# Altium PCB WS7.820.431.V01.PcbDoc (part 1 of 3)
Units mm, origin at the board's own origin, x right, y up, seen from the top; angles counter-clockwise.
Board outline 461 x 63.5 mm, 4 copper layers (Top Layer, Mid-Layer1, Mid-Layer 2, Bottom Layer); 379 components, 227 nets, 1092 pads, 3835 vias.
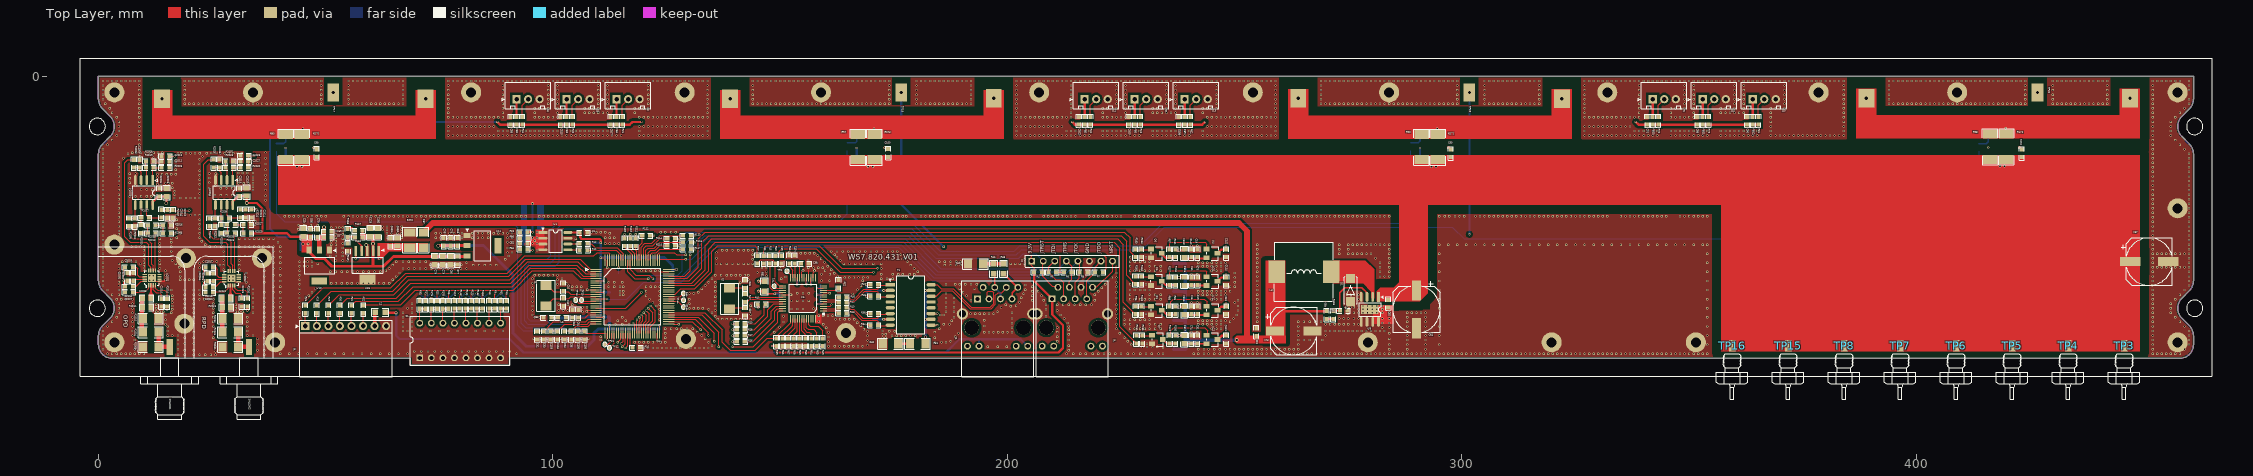
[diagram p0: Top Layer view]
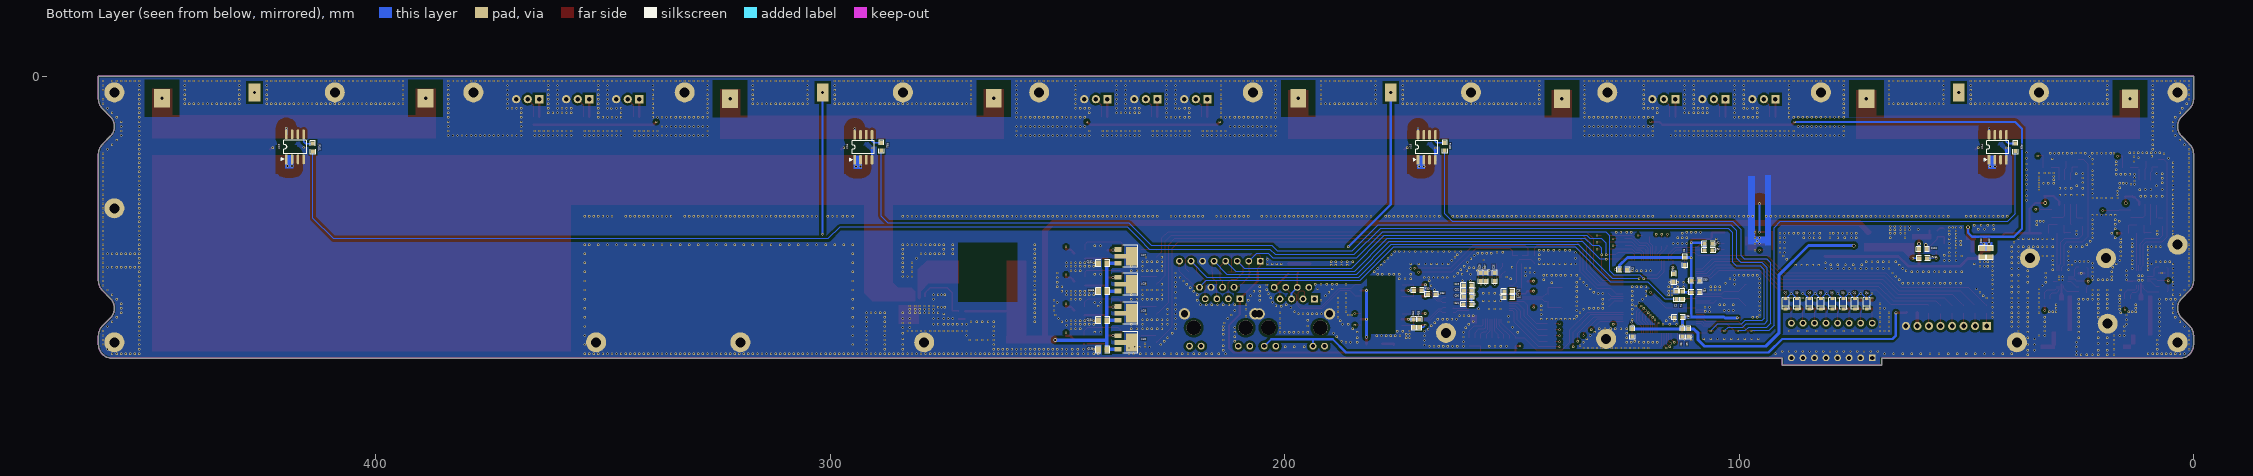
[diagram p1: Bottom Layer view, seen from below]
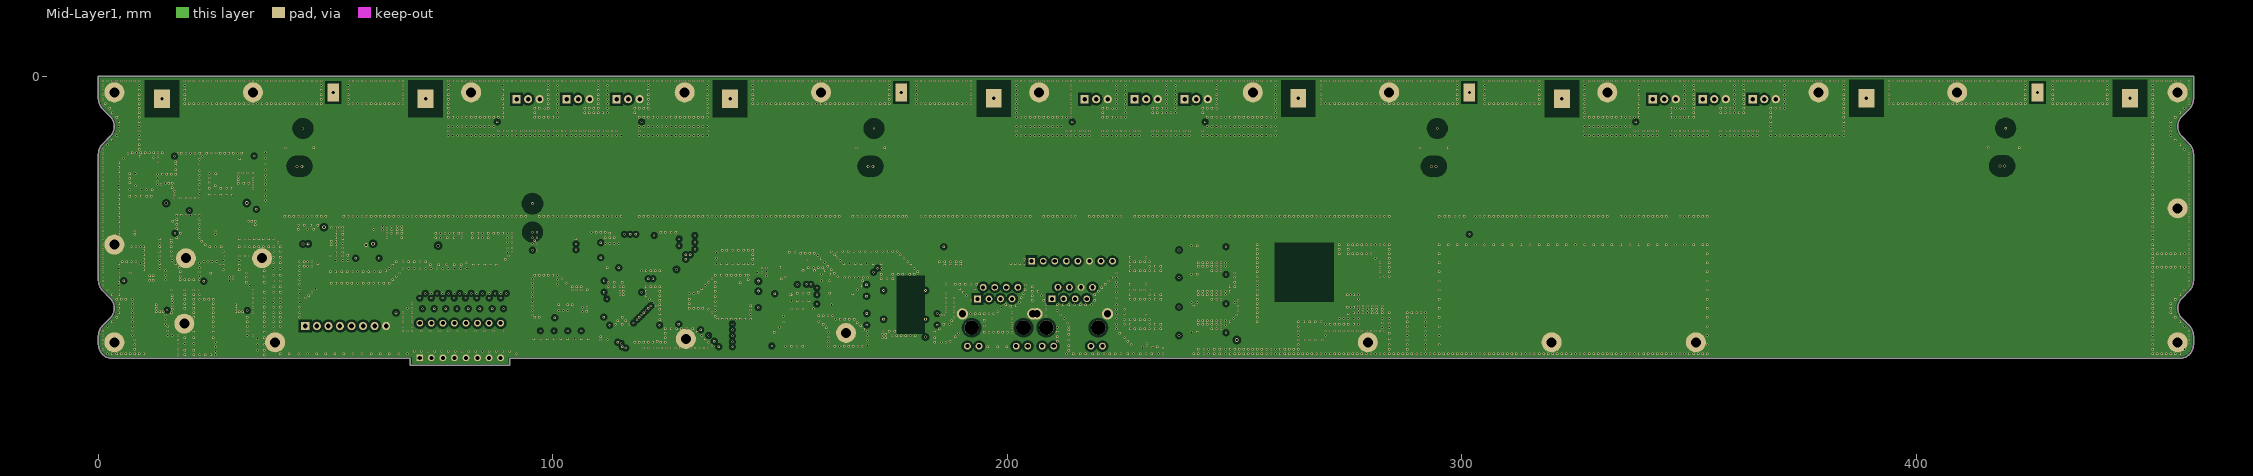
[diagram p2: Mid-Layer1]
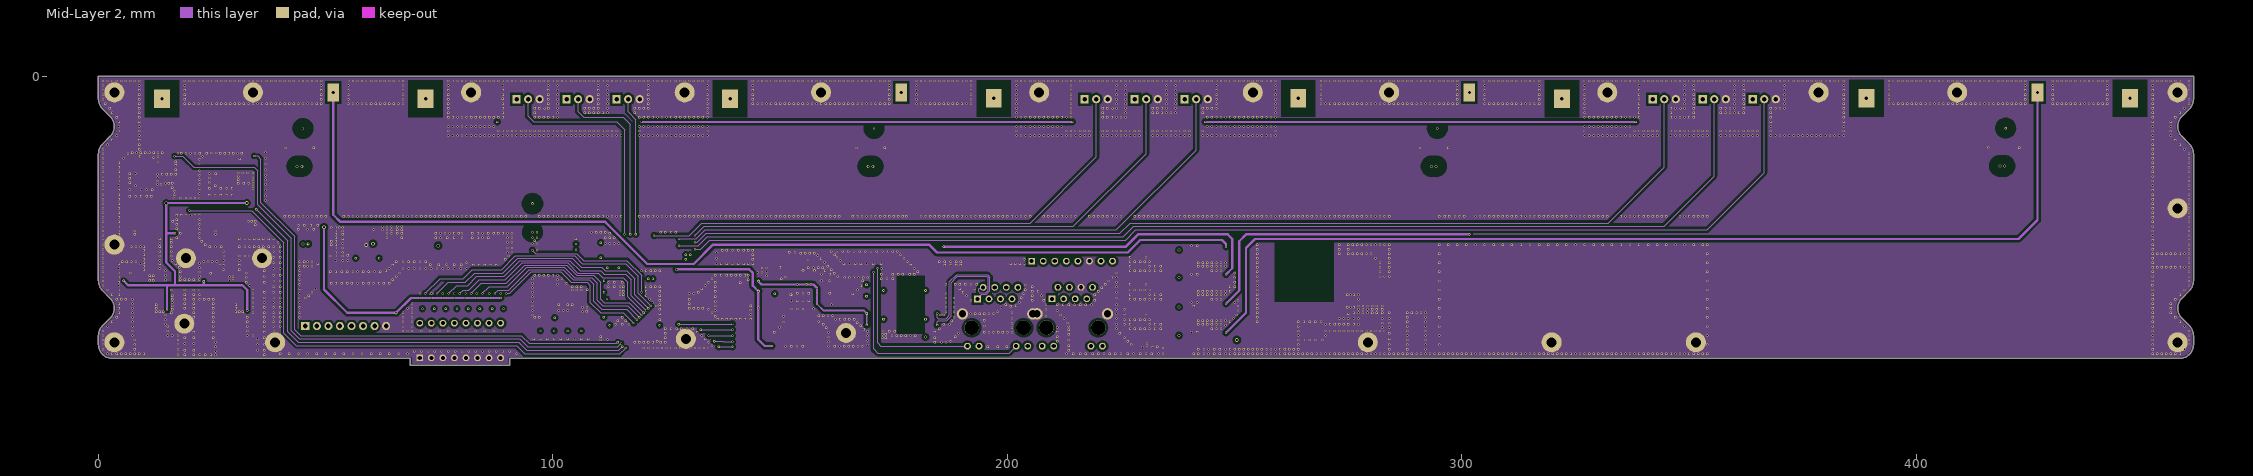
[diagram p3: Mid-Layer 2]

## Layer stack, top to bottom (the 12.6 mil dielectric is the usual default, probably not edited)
Top Solder: solder mask 0.0102, Solder Resist, Dk 3.5
Top Layer: signal copper 0.0356
Dielectric1: core 0.32, FR-4, Dk 4.8
Mid-Layer1: signal copper 0.0356
Dielectric3: prepreg 0.32, FR-4, Dk 4.8
Mid-Layer 2: signal copper 0.0356
Dielectric2: core 0.32, FR-4, Dk 4.8
Bottom Layer: signal copper 0.0356
Bottom Solder: solder mask 0.0102, Solder Resist, Dk 3.5

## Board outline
0,-57.04 cw(c3.066,-57.04) 0.898,-54.872 2.602,-53.168 ccw(c0.434,-51) 3.5,-51 ccw(c0.434,-51) 2.602,-48.832 0.898,-47.128 cw(c3.066,-44.96) 0,-44.96 0,-17.04 cw(c3.066,-17.04) 0.898,-14.872 2.602,-13.168 ccw(c0.434,-11) 3.5,-11 ccw(c0.434,-11) 2.602,-8.832 0.898,-7.128 cw(c3.066,-4.96) 0,-4.96 0,0 461,0 461,-4.96 cw(c457.934,-4.96) 460.102,-7.128 458.398,-8.832 ccw(c460.566,-11) 457.5,-11 ccw(c460.566,-11) 458.398,-13.168 460.102,-14.872 cw(c457.934,-17.04) 461,-17.04 461,-44.96 cw(c457.934,-44.96) 460.102,-47.128 458.398,-48.832 ccw(c460.566,-51) 457.5,-51 ccw(c460.566,-51) 458.398,-53.168 460.102,-54.872 cw(c457.934,-57.04) 461,-57.04 461,-59 cw(c458,-59) 458,-62 90.535,-62 90.535,-63.5 68.655,-63.5 68.655,-62 3,-62 cw(c3,-59) 0,-59

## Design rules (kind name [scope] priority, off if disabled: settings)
Clearance Clearance_4 [(InPolygon) vs InNetClass('50V')] p1: gap=2.032 ignorepadtopadclearanceinfootprint=FALSE except(0: Arc-Hole Track-Hole SMDPad-Hole THPad-Hole Via-Hole Fill-Hole Poly-Hole Region-Hole Text-Hole)
Clearance Clearance_3 [(InPolygon) vs isfill] p2: gap=1.016 ignorepadtopadclearanceinfootprint=FALSE except(0: Arc-Hole Track-Hole SMDPad-Hole THPad-Hole Via-Hole Fill-Hole Poly-Hole Region-Hole Text-Hole)
Clearance Clearance_2 [All vs OnLayer('Keep-Out Layer')] p3: gap=0.203 ignorepadtopadclearanceinfootprint=FALSE except(0: Arc-Hole Track-Hole SMDPad-Hole THPad-Hole Via-Hole Fill-Hole Poly-Hole Region-Hole Text-Hole)
Clearance Clearance_1 [All vs (InPolygon)] p4: gap=0.508 ignorepadtopadclearanceinfootprint=FALSE except(0: Arc-Hole Track-Hole SMDPad-Hole THPad-Hole Via-Hole Fill-Hole Poly-Hole Region-Hole Text-Hole)
Clearance [All] p5: gap=0.152 ignorepadtopadclearanceinfootprint=FALSE except(0: Arc-Hole Track-Hole SMDPad-Hole THPad-Hole Via-Hole Fill-Hole Poly-Hole Region-Hole Text-Hole)
ComponentClearance [All] p1: gap=0 collisioncheckmode=3 verticalgap=0 showdistances=FALSE
DiffPairsRouting DiffPair_DiffPairsRouting [All] p1: maxlimit=0.254 minlimit=0.191 mostfreqgap=0.191 toplayer_minwidth=0.191 toplayer_maxwidth=0.381 toplayer_prefwidth=0.191 midlayer1_minwidth=0.191 midlayer1_maxwidth=0.381 midlayer1_prefwidth=0.191 midlayer2_minwidth=0.191 midlayer2_maxwidth=0.381 midlayer2_prefwidth=0.191 bottomlayer_minwidth=0.191 bottomlayer_maxwidth=0.381 bottomlayer_prefwidth=0.191 maxuncoupledlength=12.7
DiffPairsRouting [All] p2: maxlimit=0.254 minlimit=0.254 mostfreqgap=0.254 toplayer_minwidth=0.381 toplayer_maxwidth=0.381 toplayer_prefwidth=0.381 midlayer1_minwidth=0.381 midlayer1_maxwidth=0.381 midlayer1_prefwidth=0.381 midlayer2_minwidth=0.381 midlayer2_maxwidth=0.381 midlayer2_prefwidth=0.381 bottomlayer_minwidth=0.381 bottomlayer_maxwidth=0.381 bottomlayer_prefwidth=0.381 maxuncoupledlength=12.7
HoleSize [All] p1: absolutevalues=TRUE maxlimit=10 minlimit=0.025 maxpercent=80.000 minpercent=20.000
HoleToHoleClearance [All] p1: gap=0 allowstackedmicrovias=TRUE
MinimumSolderMaskSliver [All] p1: minsoldermaskwidth=0
PlaneConnect [All] p1: planeconnectstyle=Direct reliefexpansion=0.508 reliefentries=4 reliefconductorwidth=0.254 reliefairgap=0.254
PolygonConnect [All] p1: connectstyle=Direct reliefconductorwidth=0.254 reliefentries=4 polygonreliefangle="90 Angle" airgapwidth=0.254
RoutingVias [All] p1: holewidth=0.305 width=0.508 viastyle="Through Hole" minholewidth=0.305 minwidth=0.508 maxholewidth=0.711 maxwidth=1.27
SilkToSilkClearance [All] p1: silktosilkclearance=0
SilkToSolderMaskClearance SilkscreenOverComponentPads [IsPad] p1: minsilkscreentomaskgap=0 clearancetoexposedcopper=TRUE
SolderMaskExpansion [All] p1: expansion=0 istentingtop=FALSE
Width DiffPair_Width [All] p1: maxlimit=2.54 minlimit=0.191 preferedwidth=0.191
Width [All] p2: maxlimit=1 minlimit=0.191 preferedwidth=0.254 midlayer1_maxwidth=0.254 midlayer2_maxwidth=0.254 minimp=50.000000 maximp=50.000000 favimp=50.000000
22 further rules are at their usual default settings.

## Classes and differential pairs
net class 50V: 28VIN 28VOUT1 28VOUT2 28VOUT3 28VOUT4
component class 1-MCU: C1 C2 C3 C4 C5 C6 C7 C8 C9 C10 C11 C71 C83 C90 C98 C99 C102 C107 C108 C109 C110 D2 D3 D4 D5 D6 D7 D8 D9 FB2 FB3 FB4 FB5 FB6 FB9 FB10 FB11 FB12 J1 J2 J3 J5 J6 J8 J9 J10 J11 J12 J13 J14 L2 R1 R2 R3 R4 R5 R6 R7 R8 R9 R10 R11 R12 R13 R14 R15 R16 R17 R18 R19 R20 R21 R22 R23 R24 R25 R26 R27 R28 R29 R30 R31 R32 R61 R62 R70 R77 R79 R81 R91 R109 R110 R111 R112 R113 R114 R115 R116 R117 R118 R119 R120 R121 R132 R133 R174 R175 R176 R177 S1 TP9 TP10 TP11 TP12 TP13 TP14 TP17 TP18 TP19 TP20 TP21 U1 U2 X1
component class 2-RJ45: C24 C25 C26 C27 C28 C29 C30 C31 C32 C33 C34 C35 C36 C37 C38 C39 C40 C41 C42 FB1 J4 R33 R34 R35 R36 R37 R38 R39 R40 R41 R42 R43 R44 R45 R46 R47 R48 R49 R50 R51 R52 R53 R54 R55 R56 R57 R58 R59 R60 T1 TP1 TP2 U5 X2
component class 4-POWER: C12 C15 C18 C19 C22 C23 C43 C52 C61 C64 C65 C66 C67 C68 C69 C70 C72 C73 C74 C75 C76 C77 C78 C79 C80 C82 C84 C85 C86 C87 C88 C89 C91 C92 C93 C94 C95 C100 C101 C103 C104 C105 C106 C114 C121 C128 C129 C132 C133 C134 C135 C141 C142 C181 C182 C183 C184 C185 D1 FB7 FB15 FB16 FB17 FB18 L4 L5 L6 Q1 Q5 Q6 Q7 R80 R82 R83 R84 R85 R86 R87 R88 R89 R90 R93 R94 R95 R97 R98 R100 R101 R103 R104 R105 R107 R123 R160 R161 R162 R165 R166 R167 R168 R169 R170 R171 R172 R173 R181 R183 R184 R231 TP3 TP4 TP5 TP6 TP7 TP8 TP15 TP16 U4 U9 U10 U11 U12 U14 U15 U18 U19 U20 U21 U25 U27 U28 U29 U30
component class 3-RF: C2001 C2002 C2003 C2004 C2005 C2006 C2007 C2008 C2009 C2010 C2011 C2012 C2013 C2014 C2015 C2016 C2017 C2018 C2019 C2020 C2021 C2022 C2023 C2024 C2025 C2026 C2027 C2028 R2002 R2003 R2004 R2005 R2006 R2007 R2008 R2009 R2010 R2011 R2012 R2013 R2014 R2015 R2016 R2017 R2018 R2019 R2020 R2021 R2023 R2024 R2025 R2026 R2027 R2028 R2029 R2030 R2031 R2032 R2033 R2034 R2035 R2036 R2037 R2038 SMA2001 SMA2002 U2001 U2002 U2003 U2004
differential pair RX1: +RX1_P -RX1_N
differential pair RX: +RX_P -RX_N
differential pair TX1: +TX1_P -TX1_N
differential pair TX: +TX_P -TX_N
differential pair W5500_RX1: +W5500_RX1_P -W5500_RX1_N
differential pair W5500_TX1: +W5500_TX1_P -W5500_TX1_N

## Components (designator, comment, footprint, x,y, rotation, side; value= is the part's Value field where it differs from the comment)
C1 "0.1uF" C0603#1 106.728,-34.354 r180 top
C2 "0.1uF" C0603#1 113.794,-48.137 r270 bottom
C3 "0.1uF" C0603#1 125.468,-42.582 r0 bottom
C4 "0.1uF" C0603#1 123.468,-56.392 r90 bottom
C5 "0.1uF" C0603#1 113.318,-52.955 r180 bottom
C6 "0.1uF" C0603#1 112.468,-56.392 r90 bottom
C7 "0.1uF" C0603#1 109.603,-47.455 r0 bottom
C8 "0.1uF" C0603#1 111.968,-40.644 r90 bottom
C9 "10uF/6.3V" C0603#1 111.213,-56.392 r90 bottom
C10 "20pF" C0603#1 102.271,-46.393 r90 top
C11 "20pF" C0603#1 102.271,-49.661 r270 top
C12 "0.1uF" C0603#2 254.75,-56.25 r90 top
C15 "1uF" C0603#2 240.439,-51.465 r90 top
C18 "1nF" C0603#2 241.753,-38.918 r270 top
C19 "1nF" C0603#2 241.753,-51.465 r270 top
C22 "10uF/10V" C0805 46.503,-38.782 r90 bottom
C23 "10uF/10V" C0805 45.114,-34.362 r270 top
C24 "0.1uF" C0603#1 150.809,-48.575 r180 bottom
C25 "10uF/6.3V" C0603#1 150.809,-47.305 r180 bottom
C26 "0.1uF" C0603#1 153.779,-44.124 r270 bottom
C27 "0.1uF" C0603#1 155.69,-44.124 r270 bottom
C28 "0.1uF" C0603#1 156.833,-44.124 r270 bottom
C29 "0.1uF" C0603#1 159.728,-45.909 r180 bottom
C30 "0.1uF" C0603#1 159.728,-48.442 r180 bottom
C31 "0.1uF" C0603#1 159.754,-50.093 r180 bottom
C32 "10uF/6.3V" C0603#1 159.728,-47.179 r180 bottom
C33 "10nF" C0603#1 167.652,-47.927 r0 bottom
C34 "22nF" C0603#1 171.55,-54.328 r90 bottom
C35 "18pF" C0603#1 142.278,-45.692 r270 top
C36 "1nF" C0603#1 146.419,-40.314 r90 top
C37 "18pF" C0603#1 142.278,-51.788 r90 top
C38 "4.7uF/6.3V" C0603#1 155.436,-41.203 r180 top
C39 "1nF" C0603#1 150.229,-40.314 r90 top
C40 "10nF" C0603#1 153.251,-40.28 r270 top
C41 "1nF/2kV" C1206 193,-41.25 r0 top
C42 "1nF/2kV" C1206 174.285,-58.809 r0 top
C43 "10uF/10V" C0805 44.817,-38.782 r90 bottom
C52 "0.1uF" C0603#2 248.104,-51.465 r270 top
C61 "1uF" C0603#2 240.439,-45.05 r90 top
C64 "100uF/63V" ECAP2SM_10R4x10R4#1 290,-51.25 r270 top
C65 "0.1uF" C0603#1 283.75,-50 r90 top
C66 "0.1uF" C0603#2 46.638,-34.464 r90 top
C67 "10uF/6.3V" C0603#2 50.465,-35.387 r0 top
C68 "10uF/6.3V" C0603#2 79,-36.4 r90 top
C69 "10uF/6.3V" C0603#2 50.465,-34.159 r0 top
C70 "1uF" C0603#2 48.179,-34.464 r90 top
C71 "0.1uF" C0603#2 340.75,-9.75 r270 top
C72 "1000uF/16V" ECAP2SM_10R4x10R4#2 263,-56 r0 top
C73 "10uF/10V" C0805 75.75,-40.5 r90 top
C74 "1uF" C0603#1 240.439,-57.878 r270 top
C75 "1nF" C0603#1 241.753,-45.05 r90 top
C76 "1uF" C0603#1 76,-36.4 r270 top
C77 "0.1uF" C0603#1 79,-40.5 r90 top
C78 "10uF/6.3V" C0603#2 77.5,-36.4 r90 top
C79 "10uF/10V" C0805 74,-40.5 r90 top
C80 "10uF/10V" C0805 77.5,-40.5 r90 top
C82 "0.1uF" C0603#1 93.575,-36.789 r180 top
C83 "0.1uF" C0603#2 109.603,-44.955 r180 bottom
C84 "0.1uF" C0603#1 105.539,-52.197 r270 top
C85 "0.1uF" C0603#2 98.808,-53.12 r180 top
C86 "10uF/6.3V" C0603#2 104.269,-52.197 r90 top
C87 "100uF/63V" ECAP2SM_10R4x10R4#1 451.25,-40.75 r0 top
C88 "0.1uF" C0603#1 48.081,-16.859 r270 top
C89 "0.1uF" C0603#1 297.598,-16.91 r270 top
C90 "0.1uF" C0603#2 362.75,-9.75 r270 top
C91 "1nF" C0603#2 241.753,-57.878 r270 top
C92 "10uF/6.3V" C0603#1 96.5,-57 r90 top
C93 "0.1uF" C0603#1 98,-57 r90 top
C94 "10uF/6.3V" C0603#1 102.5,-57 r90 top
C95 "0.1uF" C0603#1 104,-57 r90 top
C98 "0.1uF" C0603#2 351.75,-9.75 r270 top
C99 "0.1uF" C0603#2 90.75,-9.75 r270 top
C100 "0.1uF" C0603#1 173.731,-16.852 r270 top
C101 "0.1uF" C0603#2 423.25,-16.91 r90 top
C102 "0.1uF" C0603#2 215.75,-9.75 r270 top
C103 "10uF/6.3V" C0603#1 99.5,-57 r90 top
C104 "0.1uF" C0603#1 101,-57 r90 top
C105 "10uF/6.3V" C0603#1 105.5,-57 r90 top
C106 "0.1uF" C0603#1 107,-57 r90 top
C107 "0.1uF" C0603#2 112.75,-9.75 r270 top
C108 "0.1uF" C0603#2 237.75,-9.75 r270 top
C109 "0.1uF" C0603#2 226.75,-9.75 r270 top
C110 "0.1uF" C0603#2 101.75,-9.75 r270 top
C114 "0.1uF" C0603#2 248.104,-45.05 r270 top
C121 "0.1uF" C0603#2 248.104,-57.878 r270 top
C128 "10uF/50V" C1210 68.5,-36 r270 top
C129 "10uF/10V" C0805 59.788,-34.341 r270 top
C132 "10uF/10V" C0805 240.001,-41.108 r180 bottom
C133 "10uF/10V" C0805 240.001,-47.24 r180 bottom
C134 "10uF/10V" C0805 240.001,-53.655 r180 bottom
C135 "10uF/10V" C0805 240.001,-60.099 r180 bottom
C141 "1uF" C0603#2 240.439,-38.918 r90 top
C142 "0.1uF" C0603#2 248.104,-38.918 r270 top
C181 "0.1uF" C0603#2 64.25,-36.45 r90 top
C182 "1uF" C0603#2 59.585,-37.969 r180 bottom
C183 "10uF/10V" C0805 65.75,-36.45 r270 top
C184 "0.1uF" C0603#2 57.248,-35.366 r180 top
C185 "10uF/10V" C0805 61.49,-34.341 r270 top
C2001 "0.1uF" C0603#1 6.33,-44.112 r270 top
C2002 "100pF" C0603#1 7.634,-44.112 r90 top
C2003 "0.1uF" C0603#2 6.711,-41.953 r0 top
C2004 "12pF" C0603#2 6.711,-46.271 r0 top
C2005 "0.1uF" C0603#2 13.43,-25.527 r270 top
C2006 "10uF/10V" C0805 15.03,-25.527 r90 top
C2007 "20PF" C0603#2 6.711,-47.515 r180 top
C2008 "100pF" C0805 10.637,-48.774 r0 top
C2009 "0.1uF" C0603#2 9.06,-19.175 r90 top
C2010 "open" C0603#2 13.823,-49.776 r270 top
C2011 "0.1uF" C0603#2 14.742,-18.794 r180 top
C2012 "0.1uF" C0603#2 16.37,-30.239 r270 top
C2013 "1uF" C0603#2 14.742,-17.524 r180 top
C2014 "1uF" C0603#2 15.1,-30.239 r270 top
C2015 "0.1uF" C0603#1 23.992,-44.171 r270 top
C2016 "100pF" C0603#1 25.296,-44.171 r90 top
C2017 "0.1uF" C0603#2 24.373,-42.012 r0 top
C2018 "12pF" C0603#2 24.373,-46.33 r0 top
C2019 "0.1uF" C0603#2 31.005,-25.5 r270 top
C2020 "10uF/10V" C0805 32.605,-25.4 r90 top
C2021 "20PF" C0603#2 24.373,-47.575 r180 top
C2022 "100pF" C0805 28.116,-48.834 r0 top
C2023 "0.1uF" C0603#2 32.425,-30.152 r270 top
C2024 "1uF" C0603#2 33.695,-30.152 r270 top
C2025 "0.1uF" C0603#2 26.646,-19.148 r90 top
C2026 "open" C0603#2 31.5,-49.75 r270 top
C2027 "0.1uF" C0603#2 32.107,-18.762 r180 top
C2028 "1uF" C0603#2 32.107,-17.475 r180 top
D1 "SS36" DO-214AC 275.5,-47 r90 top
D2 "ESD3V3D3B" SOD-323 74.52,-49.975 r90 bottom
D3 "ESD3V3D3B" SOD-323 77.06,-49.975 r90 bottom
D4 "ESD3V3D3B" SOD-323 71.909,-49.975 r90 bottom
D5 "ESD3V3D3B" SOD-323 82.001,-49.975 r90 bottom
D6 "ESD3V3D3B" SOD-323 79.461,-49.975 r90 bottom
D7 "ESD3V3D3B" SOD-323 89.75,-50 r90 bottom
D8 "ESD3V3D3B" SOD-323 84.5,-50 r90 bottom
D9 "ESD3V3D3B" SOD-323 87.25,-50 r90 bottom
FB1 "FB_0805" L0805#1 146.52,-46.156 r90 top
FB2 "FB_0603" L0603 92,-9.75 r270 top
FB3 "FB_0603" L0603 103,-9.75 r270 top
FB4 "FB_0603" L0603 114,-9.75 r270 top
FB5 "FB_0603" L0603 217,-9.75 r270 top
FB6 "FB_0603" L0603 228,-9.75 r270 top
FB7 "FB_1206" L1206 71.5,-36 r270 top
FB9 "FB_0603" L0603 239,-9.75 r270 top
FB10 "FB_0603" L0603 342,-9.75 r270 top
FB11 "FB_0603" L0603 353,-9.75 r270 top
FB12 "FB_0603" L0603 364,-9.75 r270 top
FB15 "FB_0805" L0805#2 238.937,-51.465 r90 top
FB16 "FB_0805" L0805#2 238.937,-45.05 r90 top
FB17 "FB_0805" L0805#2 238.937,-57.878 r90 top
FB18 "FB_0805" L0805#2 238.937,-38.918 r90 top
J1 "单排排母8p" SIP8TM-2R54 205.35,-40.65 r0 top
J2 "KF2510-8P" "KF2510-8P -2R54-20R32x6R0-wanzhen" 45.516,-54.912 r0 top
J3 "RJ45插座" RJ45TH-1x1-2R54-LED 214.285,-47.659 r0 top
J4 "RJ45插座" RJ45TH-1x1-2R54-LED 197.85,-47.673 r0 top
J5 "XH2.54-3P" XH2.54mm-10R0x7R0--zhizhen 92,-5 r0 top
J6 "XH2.54-3P" XH2.54mm-10R0x7R0--zhizhen 114,-5 r0 top
J8 "XH2.54-3P" XH2.54mm-10R0x7R0--zhizhen 228,-5 r0 top
J9 "XH2.54-3P" XH2.54mm-10R0x7R0--zhizhen 342,-5 r0 top
J10 "XH2.54-3P" XH2.54mm-10R0x7R0--zhizhen 364,-5 r0 top
J11 "XH2.54-3P" XH2.54mm-10R0x7R0--zhizhen 103,-5 r0 top
J12 "XH2.54-3P" XH2.54mm-10R0x7R0--zhizhen 217,-5 r0 top
J13 "XH2.54-3P" XH2.54mm-10R0x7R0--zhizhen 239,-5 r0 top
J14 "XH2.54-3P" XH2.54mm-10R0x7R0--zhizhen 353,-5 r0 top
L2 "FB_0805" L0805#1 62.026,-51.889 r0 top
L4 "100uH" PL2SM-12R5x12R5 265.25,-43 r270 top
L6 "FB_0603" L0603 101.983,-53.12 r180 top
Q1 "MMBT2222" SOT23-3 232.774,-51.465 r180 top
Q5 "MMBT2222" SOT23-3 232.774,-45.05 r180 top
Q6 "MMBT2222" SOT23-3 232.774,-38.918 r180 top
Q7 "MMBT2222" SOT23-3 232.993,-57.878 r180 top
R1 "4.7K" R0603 112.524,-48.137 r90 bottom
R2 "4.7K" R0603 106.728,-36.843 r0 bottom
R3 "4.7K" R0603 106.728,-38.215 r0 bottom
R4 "4.7K" R0603 206.747,-43.113 r180 top
R5 "4.7K" R0603 209.907,-43.113 r0 top
R6 "4.7K" R0603 213.321,-43.113 r180 top
R7 "4.7K" R0603 220.148,-43.113 r0 top
R8 "1K" R0603 216.734,-43.113 r180 top
R9 "30Ω" R0603 87.25,-50.25 r90 top
R10 "10K" R0603 114.429,-44.327 r90 bottom
R11 "0Ω" R0603 106.728,-38.215 r180 top
R12 "0Ω" R0603 106.728,-36.843 r180 top
R13 "4.7K" R0603 86,-50.25 r270 top
R14 "30Ω" R0603 89.75,-50.25 r90 top
R15 "1K" R0603 118.366,-59.694 r180 top
R16 "30Ω" R0603 141.355,-58.392 r0 top
R17 "30Ω" R0603 141.355,-57.079 r0 top
R18 "30Ω" R0603 141.355,-55.767 r0 top
R19 "30Ω" R0603 141.355,-54.455 r0 top
R20 "4.7K" R0603 104.25,-9.75 r90 top
R21 "4.7K" R0603 115.25,-9.75 r90 top
R22 "4.7K" R0603 218.25,-9.75 r90 top
R23 "4.7K" R0603 229.25,-9.75 r90 top
R24 "4.7K" R0603 93.25,-9.75 r90 top
R25 "30Ω" R0603 77.035,-50.254 r90 top
R26 "300Ω" R0603 45.516,-51.254 r90 top
R27 "30Ω" R0603 74.495,-50.254 r90 top
R28 "300Ω" R0603 48.056,-51.254 r90 top
R29 "300Ω" R0603 50.596,-51.254 r90 top
R30 "300Ω" R0603 53.136,-51.254 r90 top
R31 "300Ω" R0603 55.676,-51.254 r90 top
R32 "300Ω" R0603 58.216,-51.254 r90 top
R33 "0Ω" R0603 170.7,-47.089 r0 bottom
R34 "49.9Ω" R0603 170.7,-54.709 r180 top
R35 "82Ω" R0603 170.7,-48.359 r0 top
R36 "49.9Ω" R0603 170.7,-52.169 r180 top
R37 "82Ω" R0603 170.7,-45.819 r0 top
R38 "10Ω" R0603 170.345,-54.328 r270 bottom
R39 "4.7K" R0603 149.187,-58.468 r270 top
R40 "30Ω" R0603 163.741,-48.562 r0 top
R41 "4.7K" R0603 145.885,-50.086 r180 top
R42 "30Ω" R0603 163.741,-49.748 r0 top
R43 "30Ω" R0603 163.741,-50.933 r0 top
R44 "30Ω" R0603 163.741,-52.118 r0 top
R45 "300Ω" R0603 147.689,-40.314 r270 top
R46 "75Ω" R0805#1 197,-42.3 r270 top
R47 "1M" R0603 142.278,-48.74 r90 top
R48 "75Ω" R0805#1 199.125,-42.3 r270 top
R49 "4.7K" R0603 159.347,-58.468 r270 top
R50 "300Ω" R0603 148.959,-40.314 r270 top
R51 "75Ω" R1206 180.254,-58.809 r0 top
R52 "12.4K" R0603 162.818,-45.648 r270 top
R53 "4.7K" R0603 158.077,-58.468 r270 top
R54 "4.7K" R0603 156.807,-58.468 r270 top
R55 "1K" R0603 151.981,-40.28 r270 top
R56 "1K" R0603 150.457,-58.468 r90 top
R57 "1K" R0603 151.727,-58.468 r90 top
R58 "1K" R0603 152.997,-58.468 r90 top
R59 "1K" R0603 154.267,-58.468 r90 top
R60 "1K" R0603 155.537,-58.468 r90 top
R61 "4.7K" R0603 88.5,-50.25 r270 top
R62 "4.7K" R0603 240.25,-9.75 r90 top
R70 "4.7K" R0603 343.25,-9.75 r90 top
R77 "0Ω" R0603 145,-40.314 r270 top
R79 "4.7K" R0603 354.25,-9.75 r90 top
R80 "6.2K 1%" R0603 270.25,-52.5 r90 top
R81 "4.7K" R0603 365.25,-9.75 r90 top
R82 "2K 1%" R0603 274,-51.5 r0 top
R83 "100KΩ 1%" R0603 93.6,-34.25 r180 top
R84 "1K" R0603 93.575,-38.059 r180 top
R85 "10K" R0603 236.904,-51.465 r90 top
R86 "6.2K 1%" R0603 93.613,-35.57 r180 top
R87 "1K" R0603 235.621,-38.918 r90 top
R88 "1K" R0603 235.59,-51.465 r90 top
R89 "0.004" R2512 41.216,-15.509 r90 top
R90 "0.004" R2512 291.171,-15.509 r90 top
R91 "4.7K" R0603 70.705,-50.254 r270 top
R93 "1K" R0603 39.191,-15.589 r270 bottom
R94 "1K" R0603 288.754,-15.462 r270 bottom
R95 "1K" R0603 228.175,-51.465 r90 top
R97 "0.004" R2512 167.122,-15.509 r90 top
R98 "0.004" R2512 416.238,-15.437 r90 top
R100 "1K" R0603 164.802,-15.462 r270 bottom
R101 "1K" R0603 413.804,-15.639 r270 bottom
R103 "1K" R0603 229.489,-51.465 r90 top
R104 "10K" R0603 236.904,-45.05 r90 top
R105 "10K" R0603 236.904,-57.878 r90 top
R107 "1K" R0603 235.621,-45.05 r90 top
R109 "30Ω" R0603 115.75,-36.5 r90 top
R110 "30Ω" R0603 117,-36.5 r90 top
R111 "30Ω" R0603 118.25,-36.5 r90 top
R112 "30Ω" R0603 120.5,-35 r0 top
R113 "30Ω" R0603 129.5,-35 r0 top
R114 "30Ω" R0603 126,-35.75 r0 top
R115 "30Ω" R0603 129.5,-36.5 r0 top
R116 "30Ω" R0603 126,-37.25 r0 top
R117 "30Ω" R0603 129.5,-38 r0 top
R118 "30Ω" R0603 79.5,-50.25 r90 top
R119 "4.7K" R0603 78.25,-50.25 r270 top
R120 "30Ω" R0603 82,-50.25 r90 top
R121 "4.7K" R0603 80.75,-50.25 r270 top
R123 "1K" R0603 235.59,-57.878 r90 top
R132 "30Ω" R0603 84.5,-50.25 r90 top
R133 "4.7K" R0603 83.25,-50.25 r270 top
R160 "1K" R0603 228.175,-44.831 r90 top
R161 "1K" R0603 228.394,-57.878 r90 top
R162 "1K" R0603 229.489,-44.831 r90 top
R165 "1K" R0603 229.708,-57.878 r90 top
R166 "3K 1%" R0603 271.75,-52.5 r270 top
R167 "6.2K 1%" R0603 57.248,-33.905 r0 top
R168 "120Ω" R0603 54.835,-34.443 r90 top
R169 "2K 1%" R0603 54.835,-37.588 r270 top
R170 "0.004" R2512 44.772,-15.509 r90 top
R171 "0.004" R2512 294.727,-15.509 r90 top
R172 "0.004" R2512 170.801,-15.509 r90 top
R173 "0.004" R2512 419.79,-15.437 r90 top
R175 "4.7K" R0603 73.242,-50.254 r270 top
R176 "4.7K" R0603 75.765,-50.254 r270 top
R177 "30Ω" R0603 71.912,-50.254 r90 top
R181 "10K" R0603 236.904,-38.918 r90 top
R183 "1K" R0603 228.175,-38.918 r90 top
R184 "1K" R0603 229.489,-38.918 r90 top
R231 "4.7K" R0603 59.5,-40 r0 bottom
R2002 "100KΩ 1%" R0603 7.949,-32.103 r270 top
R2003 "1K" R0603 7.816,-19.175 r270 top
R2004 "180Ω" R1206 11.5,-56.25 r0 top
R2005 "7.87KΩ" R0603 15.09,-34.5 r0 top
R2006 "100KΩ 1%" R0603 6.723,-32.078 r90 top
R2007 "1K" R0603 13.819,-30.193 r270 top
R2008 "1K" R0603 14.742,-20.098 r0 top
R2009 "68Ω" R1206 11.5,-59.5 r0 top
R2010 "68Ω" R1206 11.5,-53.25 r180 top
R2011 "75Ω" R0805#2 10.637,-50.75 r180 top
R2012 "0Ω" R0603 11.69,-34.5 r180 top
R2013 "100KΩ 1%" R0603 9.348,-33.576 r90 top
R2014 "open" R0603 11.69,-32.75 r180 top
R2015 "4.7K" R0603 15.093,-49.776 r90 top
R2016 "2.2KΩ" R0603 15.09,-32.75 r180 top
R2017 "100KΩ 1%" R0603 10.271,-31.091 r0 top
R2018 "open" R0603 11.27,-18.667 r180 top
R2019 "0Ω" R0603 11.27,-20.098 r0 top
R2020 "7.87KΩ" R0603 32.75,-34.5 r0 top
R2021 "100KΩ 1%" R0603 25.635,-32.102 r90 top
R2023 "100KΩ 1%" R0603 24.36,-32.102 r90 top
R2024 "1K" R0603 31.184,-30.166 r270 top
R2025 "180Ω" R1206 29,-56.25 r0 top
R2026 "1K" R0603 25.376,-19.148 r270 top
R2027 "2.2KΩ" R0603 32.75,-32.652 r180 top
R2028 "0Ω" R0603 29.161,-34.498 r180 top
R2029 "100KΩ 1%" R0603 26.985,-33.575 r90 top
R2030 "1K" R0603 32.107,-20.049 r0 top
R2031 "68Ω" R1206 29,-59.5 r0 top
R2032 "68Ω" R1206 29,-53.25 r180 top
R2033 "75Ω" R0805#2 28.15,-50.75 r180 top
R2034 "open" R0603 29.161,-32.652 r180 top
R2035 "4.7K" R0603 32.75,-49.75 r90 top
R2036 "100KΩ 1%" R0603 27.908,-31.179 r0 top
R2037 "open" R0603 28.805,-18.64 r180 top
R2038 "0Ω" R0603 28.805,-20.037 r0 top
S1 "SW-DIP8" DIP-16-KEY 70.705,-61.91 r0 top
SMA2001 "SMA-KFD-4" SMA-50KFD-4 15.633,-59.562 r270 top
SMA2002 "SMA-KFD-4" SMA-50KFD-4 33.064,-59.562 r270 top
T1 "HX1188NL" SOP16-1R27-7R11x12R7 178.727,-50.264 r0 top
TP1 "TEST" TP0R8 148.679,-46.149 r270 top
TP2 "TEST" TP0R8 151.499,-42.854 r270 top
TP3 "RTF-76-006-M4-S" FC-M4 445.75,-59.25 r270 top
TP4 "RTF-76-006-M4-S" FC-M4 433.429,-59.25 r270 top
TP5 "RTF-76-006-M4-S" FC-M4 421.107,-59.25 r270 top
TP6 "RTF-76-006-M4-S" FC-M4 408.786,-59.25 r270 top
TP7 "RTF-76-006-M4-S" FC-M4 396.464,-59.25 r270 top
TP8 "RTF-76-006-M4-S" FC-M4 384.143,-59.25 r270 top
TP9 "TEST" TP0R8 128.75,-47.75 r180 top
TP10 "TEST" TP0R8 128.75,-50.75 r180 top
TP11 "TEST" TP0R8 128.75,-49.25 r180 top
TP12 "TEST" TP0R8 112.426,-59.714 r180 top
TP13 "TEST" TP0R8 106.301,-49.204 r270 top
TP14 "TEST" TP0R8 105.031,-49.204 r270 top
TP15 "RTF-76-006-M4-S" FC-M4 371.821,-59.25 r270 top
TP16 "RTF-76-006-M4-S" FC-M4 359.5,-59.25 r270 top
TP17 "" TP2R54MM 51.662,-3.524 r0 top
TP18 "" TP2R54MM 176.662,-3.524 r0 top
TP19 "" TP2R54MM 301.662,-3.524 r0 top
TP20 "" TP2R54MM 426.662,-3.524 r0 top
TP21 "TEST" TP0R8 111.426,-58.964 r90 top
U1 "AT24C02N" SOIC8_1R27_3R9x4R9#1 100.535,-36.23 r0 top
U2 "STM32F103VET6" LQFP100_0R5_14x14 117.333,-48.781 r90 top locked
U4 "Si2369DS-T1-GE3" SOT23-3 245.038,-38.918 r180 top
U5 "W5500" TQFN48-0R5-7X7 155.029,-48.816 r180 top
U9 "LM2576HVDP-ADJ" SOIC8_1R27_3R9x4R9-1 279.75,-51.25 r270 top
U10 "LM1117S-3.3" SOT-223 48.59,-41.605 r180 top
U11 "LM1117S-3.3" SOT-223 84.5,-37.25 r270 top
U12 "Si2369DS-T1-GE3" SOT23-3 245.038,-51.465 r180 top
U14 "MAX4080SASA" SOIC8_1R27_3R9x4R9#2 43.088,-15.589 r90 bottom
U15 "MAX4080SASA" SOIC8_1R27_3R9x4R9#2 292.691,-15.589 r90 bottom
U18 "MAX4080SASA" SOIC8_1R27_3R9x4R9#2 168.739,-15.589 r90 bottom
U19 "MAX4080SASA" SOIC8_1R27_3R9x4R9#2 417.753,-15.499 r90 bottom
U20 "Si2369DS-T1-GE3" SOT23-3 245.038,-45.05 r180 top
U21 "Si2369DS-T1-GE3" SOT23-3 245.038,-57.878 r180 top
U25 "TPS73801" SOT-223-6 59.157,-41.555 r180 top
U27 "LM78L05F" SOT-89 235.183,-39.575 r270 bottom
U28 "LM78L05F" SOT-89 235.183,-52.122 r270 bottom
U29 "LM78L05F" SOT-89 235.183,-45.707 r270 bottom
U30 "LM78L05F" SOT-89 235.183,-58.535 r270 bottom
U2001 "ADL5511ACPZ" QFN16_0R50_3X3 11.79,-44.34 r90 top
U2002 "LMV358IDT" SOIC8_1R27_3R9x4R9#2 10.017,-25.554 r270 top
U2003 "ADL5511ACPZ" QFN16_0R50_3X3 29.275,-44.4 r90 top
U2004 "LMV358IDT" SOIC8_1R27_3R9x4R9#2 27.654,-25.527 r270 top
X1 "8M" CRY2SM-6R0x3R5 98.465,-48.237 r90 top
X2 "25M" CRY2SM-6R0x3R5 138.849,-48.867 r90 top

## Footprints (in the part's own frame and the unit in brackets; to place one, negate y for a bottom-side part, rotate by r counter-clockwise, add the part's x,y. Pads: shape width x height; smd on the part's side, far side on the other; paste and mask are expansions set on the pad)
C0603#1 [mm]
  rect 0.9x0.8 smd: 1(-0.85,0) 2(0.85,0)
  silkscreen extent -1.47,-0.55 1.47,0.55
C0603#2 [mm]
  rect 0.9x0.8 smd: 1(0.85,0) 2(-0.85,0)
  silkscreen extent -1.47,-0.55 1.47,0.55
C0805 [mm]
  rect 1.1x1.3 smd: 1(-0.9,0) 2(0.9,0)
  silkscreen extent -1.57,-0.76 1.57,0.76
C1206 [mm]
  rect 1.8x2 smd: 1(-1.7,0) 2(1.7,0)
  silkscreen extent -2.79,-1.19 2.79,1.19
C1210 [mm]
  rect 1.8x2.6 smd: 1(-1.7,0) 2(1.7,0)
  silkscreen extent -2.82,-1.52 2.82,1.52
CRY2SM-6R0x3R5 [mm]
  rect 2x2.5 smd: 1(-2.3,0) 2(2.3,0)
  silkscreen extent -3.4,-2.03 3.4,1.97
DIP-16-KEY [mm] "DIP; 16 Leads; Row Spacing 7.62 mm; Pitch 2.54 mm"
  rect 1.5x1.5 hole 0.9: 1(0,0)
  round 1.5 hole 0.9: 2(2.54,0) 3(5.08,0) 4(7.62,0) 5(10.16,0) 6(12.7,0) 7(15.24,0) 8(17.78,0) 9(17.78,7.62) 10(15.24,7.62) 11(12.7,7.62) 12(10.16,7.62) 13(7.62,7.62) 14(5.08,7.62) 15(2.54,7.62) 16(0,7.62)
  silkscreen extent -2.05,-1.59 19.83,9.2
DO-214AC [mm]
  rect 2x2 smd: 1(-2.5,0) 2(2.5,0)
  silkscreen extent -3.04,-1.49 3.04,1.49
ECAP2SM_10R4x10R4#1 [mm]
  rect 4.5x2 smd: 1(-4.15,0) 2(4.15,0)
  silkscreen extent -6.16,-5.21 5.08,5.21
ECAP2SM_10R4x10R4#2 [mm]
  rect 4x2 smd: 1(-4.15,0) 2(4.15,0)
  silkscreen extent -6.16,-5.21 5.08,5.21
FC-M4 [mm] "一对"
  rect 2.5x1.4 smd: 1(0,0)
  silkscreen extent 1.8,-3.48 11.77,3.44
"KF2510-8P -2R54-20R32x6R0-wanzhen" [mm]
  rect 1.8x1.8 hole 1: 1(0,0)
  round 1.8 hole 1: 2(2.54,0) 3(5.08,0) 4(7.62,0) 5(10.16,0) 6(12.7,0) 7(15.24,0) 8(17.78,0)
  silkscreen extent -2.12,-11.2 19.1,1.24
L0603 [mm]
  rect 0.9x0.8 smd: 1(0.85,0) 2(-0.85,0)
  silkscreen extent -1.47,-0.55 1.47,0.55
L0805#1 [mm]
  rect 1.2x1.3 smd: 1(-1.1,0) 2(1.1,0)
  silkscreen extent -1.88,-0.84 1.88,0.84
L0805#2 [mm]
  rect 1.1x1.3 smd: 1(-0.9,0) 2(0.9,0)
  silkscreen extent -1.57,-0.76 1.57,0.76
L1206 [mm]
  rect 1.8x2 smd: 1(-1.7,0) 2(1.7,0)
  silkscreen extent -2.79,-1.19 2.79,1.19
LQFP100_0R5_14x14 [mm]
  rect 0.22x2.5 smd: 1(6.326,7.865)
  oval 0.22x2.5 smd: 2(5.826,7.865) 3(5.326,7.865) 4(4.826,7.865) 5(4.326,7.865) 6(3.826,7.865) 7(3.326,7.865) 8(2.826,7.865) 9(2.326,7.865) 10(1.826,7.865) 11(1.326,7.865) 12(0.826,7.865) 13(0.326,7.865) 14(-0.174,7.865) 15(-0.674,7.865) 16(-1.174,7.865) 17(-1.674,7.865) 18(-2.174,7.865) 19(-2.674,7.865) 20(-3.174,7.865) 21(-3.674,7.865) 22(-4.174,7.865) 23(-4.674,7.865) 24(-5.174,7.865) 25(-5.674,7.865) 51(-5.674,-8.135) 52(-5.174,-8.135) 53(-4.674,-8.135) 54(-4.174,-8.135) 55(-3.674,-8.135) 56(-3.174,-8.135) 57(-2.674,-8.135) 58(-2.174,-8.135) 59(-1.674,-8.135) 60(-1.174,-8.135) 61(-0.674,-8.135) 62(-0.174,-8.135) 63(0.326,-8.135) 64(0.826,-8.135) 65(1.326,-8.135) 66(1.826,-8.135) 67(2.326,-8.135) 68(2.826,-8.135) 69(3.326,-8.135) 70(3.826,-8.135) 71(4.326,-8.135) 72(4.826,-8.135) 73(5.326,-8.135) 74(5.826,-8.135) 75(6.326,-8.135)
  oval 2.5x0.22 smd: 26(-7.674,5.865) 27(-7.674,5.365) 28(-7.674,4.865) 29(-7.674,4.365) 30(-7.674,3.865) 31(-7.674,3.365) 32(-7.674,2.865) 33(-7.674,2.365) 34(-7.674,1.865) 35(-7.674,1.365) 36(-7.674,0.865) 37(-7.674,0.365) 38(-7.674,-0.135) 39(-7.674,-0.635) 40(-7.674,-1.135) 41(-7.674,-1.635) 42(-7.674,-2.135) 43(-7.674,-2.635) 44(-7.674,-3.135) 45(-7.674,-3.635) 46(-7.674,-4.135) 47(-7.674,-4.635) 48(-7.674,-5.135) 49(-7.674,-5.635) 50(-7.674,-6.135) 76(8.326,-6.135) 77(8.326,-5.635) 78(8.326,-5.135) 79(8.326,-4.635) 80(8.326,-4.135) 81(8.326,-3.635) 82(8.326,-3.135) 83(8.326,-2.635) 84(8.326,-2.135) 85(8.326,-1.635) 86(8.326,-1.135) 87(8.326,-0.635) 88(8.326,-0.135) 89(8.326,0.365) 90(8.326,0.865) 91(8.326,1.365) 92(8.326,1.865) 93(8.326,2.365) 94(8.326,2.865) 95(8.326,3.365) 96(8.326,3.865) 97(8.326,4.365) 98(8.326,4.865) 99(8.326,5.365) 100(8.326,5.865)
  silkscreen extent -5.89,-6.35 6.65,10.08
PL2SM-12R5x12R5 [mm]
  rect 5x3.6 smd: 1(0,6) 2(0,-6)
  silkscreen extent -6.5,-6.5 6.5,6.5
QFN16_0R50_3X3 [mm]
  rect 0.9x0.3 smd: 1(-1.6,0.75) 2(-1.6,0.25) 3(-1.6,-0.25) 4(-1.6,-0.75) 9(1.6,-0.75) 10(1.6,-0.25) 11(1.6,0.25) 12(1.6,0.75)
  rect 0.3x0.9 smd: 5(-0.75,-1.6) 6(-0.25,-1.6) 7(0.25,-1.6) 8(0.75,-1.6) 13(0.75,1.6) 14(0.25,1.6) 15(-0.25,1.6) 16(-0.75,1.6)
  rect 1.75x1.75 smd: 17(0,0)
  silkscreen extent -2.04,-1.55 1.55,1.55
R0603 [mm]
  rect 0.9x0.8 smd: 1(-0.85,0) 2(0.85,0)
  silkscreen extent -1.47,-0.55 1.47,0.55
R0805#1 [mm]
  rect 1.2x1.3 smd: 1(-1.1,0) 2(1.1,0)
  silkscreen extent -1.88,-0.84 1.88,0.84
R0805#2 [mm]
  rect 1.1x1.3 smd: 1(-0.9,0) 2(0.9,0)
  silkscreen extent -1.57,-0.76 1.57,0.76
R1206 [mm]
  rect 1.8x2 smd: 1(-1.7,0) 2(1.7,0)
  silkscreen extent -2.79,-1.19 2.79,1.19
R2512 [mm]
  rect 2x3.2 smd: 1(-2.8,0) 2(2.8,0)
  silkscreen extent -3.99,-1.7 3.91,1.7
RJ45TH-1x1-2R54-LED [mm]
  rect 1.5x1.5 hole 0.9: 1(-4.445,-1.27)
  round 1.5 hole 0.9: 2(-3.175,1.27) 3(-1.905,-1.27) 4(-0.635,1.27) 5(0.635,-1.27) 6(1.905,1.27) 7(3.175,-1.27) 8(4.445,1.27) 9(-6.63,-11.68) 10(-4.09,-11.68) 11(4.09,-11.68) 12(6.63,-11.68)
  round 2.5 hole 1.6: 13(-7.75,-4.57) 14(7.75,-4.57)
  round 3.25 hole 3.25 unplated: 15(-5.715,-7.62) 16(5.715,-7.62)
  silkscreen extent -7.94,-18.42 7.94,2.73
SIP8TM-2R54 [mm] "Connector; Header; 8 Position"
  rect 1.5x1.5 hole 0.9: 1(0,0)
  round 1.5 hole 0.9: 2(2.54,0) 3(5.08,0) 4(7.62,0) 5(10.16,0) 6(12.7,0) 7(15.24,0) 8(17.78,0)
  silkscreen extent -1.37,-1.3 19.23,1.3
SMA-50KFD-4 [mm] "SMA-JB3C"
  rect 3.5x1.4 smd: 1(0,0.06)
  silkscreen extent 2.37,-6.29 15.9,6.41
SOD-323 [mm]
  rect 0.65x0.85 smd: 1(-1.15,0) 2(1.15,0)
  silkscreen extent -1.25,-0.76 1.27,0.76
SOIC8_1R27_3R9x4R9#1 [mm]
  rect 1.981x0.6 smd: 1(-2.75,1.905)
  oval 1.981x0.6 smd: 2(-2.75,0.635) 3(-2.75,-0.635) 4(-2.75,-1.905) 5(2.75,-1.905) 6(2.75,-0.635) 7(2.75,0.635) 8(2.75,1.905)
  silkscreen extent -3.02,-2.45 1.47,2.99
SOIC8_1R27_3R9x4R9#2 [mm]
  rect 2.15x0.6 smd: 1(-2.75,1.905)
  oval 2.15x0.6 smd: 2(-2.75,0.635) 3(-2.75,-0.635) 4(-2.75,-1.905) 5(2.75,-1.905) 6(2.75,-0.635) 7(2.75,0.635) 8(2.75,1.905)
  silkscreen extent -3.02,-2.45 1.47,2.99
SOIC8_1R27_3R9x4R9-1 [mm]
  rect 2.15x0.6 smd: 1(-2.75,1.905)
  oval 2.15x0.6 smd: 2(-2.75,0.635) 3(-2.75,-0.635) 4(-2.75,-1.905) 5(2.75,-1.905) 6(2.75,-0.635) 7(2.75,0.635) 8(2.75,1.905)
  rect 2x3.8 smd: 9(0,0)
  silkscreen extent -3.02,-2.45 1.47,2.99
SOP16-1R27-7R11x12R7 [mm]
  rect 2x0.76 smd: 1(-4.5,4.445)
  oval 2x0.76 smd: 2(-4.5,3.175) 3(-4.5,1.905) 4(-4.5,0.635) 5(-4.5,-0.635) 6(-4.5,-1.905) 7(-4.5,-3.175) 8(-4.5,-4.445) 9(4.5,-4.445) 10(4.5,-3.175) 11(4.5,-1.905) 12(4.5,-0.635) 13(4.5,0.635) 14(4.5,1.905) 15(4.5,3.175) 16(4.5,4.445)
  silkscreen extent -4.84,-6.4 3.1,6.4
SOT23-3 [mm]
  rect 1.3x1 smd: 1(1.2,-0.95) 2(1.2,0.95) 3(-1.2,0)
  silkscreen extent -1.34,-1.5 1.2,1.5
SOT-89 [mm]
  rect 1x1.5 smd: 1(-1.5,-1.45) 3(1.5,-1.45)
  rect 1x4 smd: 2(0,-0.2)
  rect 4x2.4 smd: 4(0,1.45)
  silkscreen extent -2.4,-0.45 2.4,2.85
SOT-223 [mm]
  rect 1.1x1.55 smd: 1(-2.3,-3.375) 2(0,-3.375) 3(2.3,-3.375)
  rect 3.45x1.55 smd: 4(0,3.375)
  silkscreen extent -3.7,-3.65 3.35,1.85
SOT-223-6 [mm]
  rect 0.55x2.2 smd: 1(-2.54,-3.1) 2(-1.27,-3.1) 3(0,-3.1) 4(1.27,-3.1) 5(2.54,-3.1)
  rect 3.5x2.2 smd: 6(0,3.1)
  silkscreen extent -3.7,-3.65 3.35,1.7
TP0R8 [mm]
  round 0.8 smd: 1(0,0)
  silkscreen extent -0.48,-0.48 0.48,0.48
TP2R54MM [mm]
  rect 2.54x4 hole 0.7: 1(0,0)
TQFN48-0R5-7X7 [mm]
  rect 1.6x0.22 smd: 1(-4.5,2.75) 2(-4.5,2.25) 3(-4.5,1.75) 4(-4.5,1.25) 5(-4.5,0.75) 6(-4.5,0.25) 7(-4.5,-0.25) 8(-4.5,-0.75) 9(-4.5,-1.25) 10(-4.5,-1.75) 11(-4.5,-2.25) 12(-4.5,-2.75) 25(4.5,-2.75) 26(4.5,-2.25) 27(4.5,-1.75) 28(4.5,-1.25) 29(4.5,-0.75) 30(4.5,-0.25) 31(4.5,0.25) 32(4.5,0.75) 33(4.5,1.25) 34(4.5,1.75) 35(4.5,2.25) 36(4.5,2.75)
  rect 0.22x1.6 smd: 13(-2.75,-4.5) 14(-2.25,-4.5) 15(-1.75,-4.5) 16(-1.25,-4.5) 17(-0.75,-4.5) 18(-0.25,-4.5) 19(0.25,-4.5) 20(0.75,-4.5) 21(1.25,-4.5) 22(1.75,-4.5) 23(2.25,-4.5) 24(2.75,-4.5) 37(2.75,4.5) 38(2.25,4.5) 39(1.75,4.5) 40(1.25,4.5) 41(0.75,4.5) 42(0.25,4.5) 43(-0.25,4.5) 44(-0.75,4.5) 45(-1.25,4.5) 46(-1.75,4.5) 47(-2.25,4.5) 48(-2.75,4.5)
  silkscreen extent -4.72,-3.06 3.06,3.65
XH2.54mm-10R0x7R0--zhizhen [mm]
  rect 1.8x1.8 hole 1: 1(0,0)
  round 1.8 hole 1: 2(2.54,0) 3(5.08,0)
  silkscreen extent -3.31,-2.1 7.5,3.7

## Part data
C1 C2 C3 C4 C5 C6 C7 C8 C12 C24 C26 C27 C28 C29 C30 C31 C52 C65 C66 C77 C82 C83 C84 C85 C88 C89 C93 C95 C100 C101 C104 C106 C114 C121 C142 C181 C184 C2001 C2003 C2005 C2009 C2011 C2012 C2015 C2017 C2019 C2023 C2025 C2027: library part 0.1uF贴片电容, "贴片电容_GRM188R71H104KA01D_0.1uF±10%,50V,0603"
C9 C25 C32 C67 C68 C69 C78 C86 C92 C94 C103 C105 C2013 C2028: library part 10uF贴片电容, "贴片电容_GRM188R60J106ME47D_10uF±20%,6.3V,0603"
C10 C11: library part 20pF贴片电容, "贴片电容_GRM188C1H200JB01D_20pF±5%,50V,0603"
C15 C61 C70 C74 C76 C141 C182: library part 1uF贴片电容, "贴片电容_GRM188R61A105KA61D_1uF±10%,10V,0603"
C18 C19 C36 C39 C75 C91 C2010 C2026: library part 1000pF贴片电容, "贴片电容_GRM188R71H102KA01_1000pF±10%,50V,0603"
C22 C23 C43 C73 C79 C80 C129 C132 C133 C134 C135 C183 C185 C2006 C2020: library part 10uF贴片电容, "贴片电容_GRM21BR61A106KE19L_10uF±10%,10V,0805"
C33 C40: library part 0.1uF贴片电容, "C0603C103K5RAC_10nF±10%,50V,0603", MPN=KEMET
C34: library part 27nF贴片电容, "贴片电容_22nF±5%,50V,0603"
C35 C37: library part 18pF贴片电容, "贴片电容_GRM1885C1H180JA01D_18pF±5%,50V,0603"
C38: library part 1uF贴片电容, "GRM188R61C475K_4.7uF±10%,16V,0603", MPN=Murata
C41 C42: library part 10uF贴片电容, "贴片电容_C1206C102J5GAC _1000pF±5%,50V,1206", MPN=KEMET
C64 C87: "贴片电解电容_VEJ101M1JTR-1010_100uF/63V,±20%,表贴D10*H10"
C71 C90 C98 C99 C102 C107 C108 C109 C110: "GRM188R71H104KA01D", MPN=MURATA
C72: "贴片电解电容_VE102M1CTR-1010_1000uF/16V,±20%,表贴10*10"
C128: library part 10uF贴片电容, "贴片电容_GRM32ER71H106KA12L_10uF±10%,50V,1210"
C2002 C2016: library part 1000pF贴片电容, "贴片电容_100pF±10%,50V,0603"
C2004 C2018: library part 10pF贴片电容, "GRM1885C1H390JA01D_39pF±5%,50V,0603"
C2007 C2021: library part 10pF贴片电容, "贴片电容_GRM1885C1H680JA01D_0603,68PF,50V,±5％,COG", MPN=Murata
C2008 C2022: library part 100pF贴片电容, "贴片电容_GRM2165C1H101JA01D_100pF±5%,50V,0805"
C2014 C2024: library part 10uF贴片电容
D1: library part 肖特基整流二极管_SS36, "肖特基整流二极管_SS36_封装SMA,3A/60V"
D2 D3 D4 D5 D6 D7 D8 D9: library part ESD5B5.0ST1G, "ESD_ESD3V3D3B_SOD-323,3.3V,双管"
FB1 FB15 FB16 FB17 FB18 L2: library part 0805贴片磁珠, "贴片磁珠_600R,0805"
FB2 FB3 FB4 FB5 FB6 FB9 FB10 FB11 FB12 L6: library part 0603贴片磁珠, "贴片磁珠_100R,0603"
FB7: library part 1206贴片磁珠, "贴片磁珠_30R,6A,1206"
J1: library part 8p-2.54单排母座, "连接器_单排排母座8p_直插,间距2.54mm", MPN=WS
J2: library part KF2510-8P弯针, "连接器_KF2510-8P_90°弯针,间距2.54mm"
J3 J4: library part RJ45弯脚带灯, "RJ45插座_1*1,带左黄右绿灯,弯脚", MPN=朱迅
J5 J6 J8 J9 J10 J11 J12 J13 J14: "连接器_XH2.54-3P_弯针,间距2.54mm"
L4: library part 100uH贴片功率电感, "贴片功率电感_SLF12575T-101M1R9-PF_100uH±20%,额定电流1.9A,12.5x12.5"
Q1 Q5 Q6 Q7: "NPN三极管_MMBT2222_表贴SOT23"
R1 R2 R3 R4 R5 R6 R7 R13 R20 R21 R22 R23 R24 R39 R41 R49 R53 R54 R61 R62 R70 R79 R81 R91 R119 R121 R133 R175 R176 R231 R2015 R2035: library part 4.7K贴片电阻, "贴片电阻_4.7K±5%,0603"
R8 R15 R55 R56 R57 R58 R59 R60 R84 R87 R88 R93 R94 R95 R100 R101 R103 R107 R123 R160 R161 R162 R165 R183 R184 R2003 R2026: library part 1K贴片电阻, "贴片电阻_1K±5%,0603"
R9 R14 R25 R27 R118 R120 R132 R177: library part 0Ω贴片电阻, "贴片电阻_30Ω±5%,0603"
R10 R85 R104 R105 R181: library part 10K贴片电阻, "贴片电阻_10K±5%,0603"
R11 R12 R33 R77 R2012 R2014 R2019 R2028 R2034 R2038: library part 0Ω贴片电阻, "贴片电阻_0Ω±5%,0603"
R16 R17 R18 R19 R40 R42 R43 R44 R109 R110 R111 R112 R113 R114 R115 R116 R117: library part 30Ω贴片电阻, "贴片电阻_30Ω±5%,0603"
R26 R28 R29 R30 R31 R32 R45 R50: library part 300Ω贴片电阻, "贴片电阻_300Ω±5%,0603"
R34 R36: library part 51Ω贴片电阻, "贴片电阻_49.9Ω±1%,0603"
R35 R37: library part 51Ω贴片电阻, "贴片电阻_82Ω±1%,0603"
R38: library part 10Ω贴片电阻, "贴片电阻_10Ω±5%,0603"
R46 R48 R2011 R2033: library part 75Ω贴片电阻, "贴片电阻_75Ω±5%,0805"
R47: library part 1M贴片电阻, "贴片电阻_1M±5%,0603"
R51: library part 75Ω贴片电阻, "贴片电阻_75Ω±5%,1206"
R52: library part 12K贴片电阻, "贴片电阻_12.4K±1%,0603"
R80 R167: library part 6.2K贴片电阻, "贴片电阻_6.2K±5%,0603"
R82 R169: library part 2K贴片电阻, "贴片电阻_2K±5%,0603"
R83: library part 12.4K贴片电阻, "贴片电阻_12.4K±1%,0603"
R86: library part 1.5K贴片电阻, "贴片电阻_1.5K±5%,0603"
R89 R90 R97 R98 R170 R171 R172 R173: library part 0.004Ω检流电阻-标准封装, "贴片电阻_LR12DTDSR004_0.004±5%,2W,2512"
R166: library part 3K贴片电阻, "贴片电阻_3K±5%,0603"
R168: library part 120Ω贴片电阻, "贴片电阻_120Ω±5%,0603"
R2002 R2006 R2013 R2017 R2021 R2023 R2029 R2036: library part 430Ω贴片电阻
R2004 R2025: library part 56Ω贴片电阻, "贴片电阻_1206,180Ω,±5％"
R2005 R2020: library part 0Ω贴片电阻, "0603,7.87KΩ,±1％"
R2007 R2008 R2024 R2030: library part 10K贴片电阻, "贴片电阻_1K±5%,0603"
R2009 R2010 R2031 R2032: library part 56Ω贴片电阻, "贴片电阻_68Ω±5%,1206"
R2016 R2027: library part 0Ω贴片电阻, "0603,2.2KΩ,±1％"
R2018 R2037: library part 0Ω贴片电阻
S1: "4009 Series DIP Switch, Raised actuator"
SMA2001 SMA2002: library part SMA-50KFD-4, "射频同轴连接器_SMA-KFD-4"
T1: "网络变压器_HX1188NL_百兆,SOIC16"
TP1 TP2 TP9 TP10 TP11 TP12 TP13 TP14 TP21: library part TP0.8mm, "表贴测试点0.8mm"
TP3 TP4 TP5 TP6 TP7 TP8 TP15 TP16 TP17 TP18 TP19 TP20: library part TP2mm, "表贴测试点1mm"
U1: "EEPROM_AT24C02N_SOIC8"
U2: library part STM32F103VET, "MCU_STM32F103VET6_32 bit, LQFP100"
U4 U12 U20 U21: "P-MOS_Si2369DS-T1-GE3_SOT23"
U5: "以太网控制器_W5500_LQFP48"
U9: "稳压集成电路_LM2576HVDP-ADJ_3A输出,SOIC8"
U10 U11: "LDO_LM1117S-3.3_1A输出,SOT223"
U14 U15 U18 U19: library part MAX4080TASA, "电流检测放大器_MAX4080SASA_SOIC8"
U25: library part TPS73701DCQ, "LDO_TPS73801_1A输出,SOT223-6"
U27 U28 U29 U30: "功率放大器_LM78L05F_5V输出,100mA输出,SOT89"
U2001 U2003: "检波器_ADL5511ACPZ_DC~6GHz,LFCSP16"
U2002: library part OP284
U2004: library part LM358, "运算放大器_LM358_SOIC8"
X1: library part 8M贴片无源晶体, "贴片无源晶体_8MHz,封装6035"
X2: library part 25M贴片无源晶体, "贴片无源晶体_25MHz,30ppm,6035封装"

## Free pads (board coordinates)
  round 4.4 hole 2.2: ""(3.5,-58.5) ""(3.5,-37) ""(3.5,-3.5) ""(18.88,-54.4) ""(19.25,-40) ""(34,-3.5) ""(36,-40) ""(38.88,-58.5) ""(82,-3.5) ""(129,-3.5) ""(129.25,-57.75) ""(159,-3.5) ""(164.5,-56.443) ""(207,-3.5) ""(254,-3.5) ""(279.31,-58.5) ""(284,-3.5) ""(319.75,-58.5) ""(332,-3.5) ""(351.5,-58.5) ""(378.5,-3.5) ""(409,-3.5) ""(457.5,-58.5) ""(457.5,-29) ""(457.5,-3.5)
  rect 3.5x4 hole 0.7: ""(14,-4.921) ""(72,-4.921) ""(139,-4.921) ""(197,-4.813) ""(264,-4.813) ""(322,-4.921) ""(389,-4.794) ""(447,-4.794)

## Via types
v1: diameter 0.508, hole 0.305, Top Layer to Bottom Layer, tented both sides, 3797 vias
v2: diameter 0.66, hole 0.406, Top Layer to Bottom Layer, tented both sides, 20 vias
v3: diameter 0.6, hole 0.305, Top Layer to Bottom Layer, tented both sides, 10 vias
v4: diameter 0.813, hole 0.508, Top Layer to Bottom Layer, tented both sides, 7 vias
v5: diameter 0.508, hole 0.3, Top Layer to Bottom Layer, tented both sides, 1 vias

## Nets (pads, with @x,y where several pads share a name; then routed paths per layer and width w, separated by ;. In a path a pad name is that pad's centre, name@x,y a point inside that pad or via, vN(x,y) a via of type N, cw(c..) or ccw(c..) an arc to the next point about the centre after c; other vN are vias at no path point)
3.3VADD: C26.2 C27.2 C28.2 C29.2 C30.2 C31.2 C32.2 FB1.2 R34.2 R36.2 R38.2 U5.4 U5.8 U5.11 U5.15 U5.17 U5.21 | length 54.9
  Top Layer w0.254: v1(153.779,-45.775) U5.21@153.779,-44.316 ; v1(155.779,-45.751) U5.17@155.779,-44.316 ; v1(156.779,-45.751) U5.15@156.779,-44.316 ; v1(158.099,-50.066) U5.4@159.529,-50.066 ; v1(158.099,-48.066) U5.8@159.529,-48.066 ; v1(158.099,-46.566) U5.11@159.529,-46.566
  Top Layer w0.381: v1(169.049,-54.709) R34.2@169.85,-54.709 ; v3(169.075,-52.144) 169.202,-52.144 169.227,-52.169 R36.2@169.85,-52.169
  Top Layer w0.508: v2(145.192,-45.056) FB1.2@146.52,-45.056
  Mid-Layer 2 w0.381: v1(158.099,-50.066) 159.552,-51.519 168.451,-51.519 169.049,-52.118 v1(169.049,-54.709)
  Mid-Layer 2 w0.508: v2(145.192,-45.056) 145.911,-45.775 148.324,-45.775 ; 146.291,-45.775 148.324,-45.775 ; v1(158.099,-50.066) v1(158.099,-48.066) v1(158.099,-46.566) 157.308,-45.775 v1(153.779,-45.775) 152.007,-45.775 148.324,-45.775
  Bottom Layer w0.254: v3@169.049,-52.169 v3(169.075,-52.144)
  Bottom Layer w0.381: v1(169.049,-54.709) 169.518,-55.178 R38.2@170.345,-55.178
  Bottom Layer w0.508: v1(153.779,-45.775) C26.2@153.779,-44.974 ; v1(155.779,-45.751) C27.2@155.779,-45.063 ; v1(156.779,-45.751) C28.2@156.779,-45.155 ; v1(158.099,-50.066) C31.2@158.877,-50.066 ; v1(158.099,-48.066) C30.2@158.703,-48.066 ; v1(158.099,-46.566) 158.848,-46.566 ; C31.2@158.878,-50.066 C30.2@158.878,-48.442 C32.2@158.878,-47.179 C29.2@158.878,-45.909
3.3VCC: C1.2 C3.2 C4.2 C5.2 C6.2 C7.2 C8.2 C9.2 C24.2 C25.2 C68.2 C76.2 C78.2 C83.2 C85.2 FB1.1 J1.1 J3.1 L6.1 R1.2 R2.2 R3.2 R4.2 R5.2 R6.2 R7.2 R39.2 R41.2 R49.2 R53.2 R54.2 U1.8 U2.6 U2.11 U2.22 U2.28 U2.50 U2.75 U2.100 U5.28 U11.2 | length 317.1
  Top Layer w0.254: U2.22@109.468,-52.955 v1(111.198,-52.955) ; U2.11@109.468,-47.455 v1(111.254,-47.455) ; U2.6@109.468,-44.955 v1(111.254,-44.955) ; v1(110.531,-39.858) 111.451,-39.858 111.468,-39.875 U2.100@111.468,-40.455 ; U2.28@112.468,-56.455 v1(112.468,-54.725) ; U2.50@123.468,-56.455 v1(123.468,-54.725) ; U2.75@125.468,-42.455 v2(127.205,-42.455) ; v1(148.832,-47.807) 149.073,-47.566 U5.28@150.529,-47.566 ; 156.75,-60.75 156.807,-60.693 R54.2@156.807,-59.318 R53.2@158.077,-59.318 R49.2@159.347,-59.318 ; R4.2@205.897,-43.113 205.897,-42.199 205.223,-41.525 205.223,-39.634 205.507,-39.35 211.5,-39.35 ; R5.2@210.757,-43.113 211.614,-43.113 ; R6.2@212.471,-43.113 211.614,-43.113 ; R7.2@220.998,-43.113 221.759,-42.353 221.759,-39.883 221.225,-39.35 211.5,-39.35 ; 211.5,-39.35 211.614,-39.463 211.614,-43.113
  Top Layer w0.381: C85.2@99.658,-53.12 v1(100.383,-53.12) L6.1@101.133,-53.12 ; FB1.1@146.52,-47.256 147.071,-47.807 v1(148.832,-47.807)
  Top Layer w0.508: U1.8@103.285,-34.325 C1.2@105.849,-34.325 ; C1.2@105.878,-34.354 106,-34.476 106,-35.452 106.298,-35.75 110.233,-35.75 110.531,-36.048 v1(110.531,-36.573) ; v1(145.192,-50.855) R41.2@145.192,-50.244 ; v1@148.239,-59.318 R39.2@149.187,-59.318 149.187,-60.452 149.484,-60.75 156.75,-60.75 211.25,-60.75 212.25,-59.75 212.25,-54.75 209.84,-52.34 J3.1@209.84,-48.929 205.897,-44.987 R4.2@205.897,-43.113
  Top Layer w0.635: v4(74.739,-37.223) 74.752,-37.237 81.112,-37.237 U11.2@81.125,-37.25 ; v2(145.192,-47.256) FB1.1@146.52,-47.256
  Mid-Layer 2 w0.508: v2(127.205,-42.455) 143.205,-42.455 144,-43.25 144,-46.064 v2(145.192,-47.256) v1(145.192,-50.855) 145.192,-57.883 146.615,-59.306 v1(148.197,-59.306)
  Bottom Layer w0.508: C7.2@110.593,-47.455 v1(111.254,-47.455) R1.2@112.5,-47.455 ; C83.2@110.593,-44.955 v1(111.254,-44.955) ; C4.2@123.468,-55.542 v1(123.468,-54.725) ; v1(148.832,-47.807) 149.832,-47.807 ; C24.2@149.832,-48.575 149.832,-47.807 ; C25.2@149.832,-47.305 149.832,-47.807
  Bottom Layer w0.635: v4(74.739,-37.223) 84.723,-37.223 91.25,-43.75 91.25,-56.5 94.114,-59.364 107.636,-59.364 109,-58 109,-56.5 109.958,-55.542 C9.2@111.213,-55.542 C6.2@112.468,-55.542 ; v1(100.383,-53.12) 103.13,-53.12 103.295,-52.955 110.531,-52.955 ; R3.2@107.578,-38.215 R2.2@107.578,-37.029 ; R2.2@107.578,-36.593 110.531,-36.593 v1(110.531,-39.858) ; C8.2@111.968,-39.794 C8.2@111.936,-39.826 ; C4.2@123.468,-55.542 C6.2@112.468,-55.542 ; C3.2@126.318,-42.582 126.361,-42.539 126.361,-41.611 124.576,-39.826 C8.2@111.936,-39.826 ; C3.2@126.368,-42.582 126.49,-42.46 127.2,-42.46 v2(127.205,-42.455) ; 110.531,-52.955 v1(110.531,-39.858) ; 110.531,-52.955 v1(111.198,-52.955) C5.2@112.468,-52.955 v1(112.468,-54.725) C6.2@112.468,-55.542 ; v1(110.531,-39.858) 111.904,-39.858 C8.2@111.936,-39.826
  Bottom Layer w0.762: R2.2@107.578,-37.029 R2.2@107.578,-36.843
3.3VCC1: C67.2 C69.2 C70.2 C71.1 C90.1 C98.1 C99.1 C102.1 C107.1 C108.1 C109.1 C110.1 FB2.1 FB3.1 FB4.1 FB5.1 FB6.1 FB9.1 FB10.1 FB11.1 FB12.1 J4.10 J4.12 L2.2 R13.1 R20.1 R21.1 R22.1 R23.1 R24.1 R61.1 R62.1 R70.1 R79.1 R81.1 R91.1 R119.1 R121.1 R133.1 R175.1 R176.1 U10.2 | length 575
  Top Layer w0.508: L2.2@63.126,-51.889 63.207,-51.971 65.471,-51.971 v2(65.5,-52) ; R91.1@70.705,-49.404 v1(70.705,-48.756) ; R175.1@73.242,-49.404 v1(73.242,-48.756) ; R176.1@75.765,-49.404 v1(75.765,-48.756) ; v1(87.75,-10) 88.35,-10.6 C99.1@90.75,-10.6 FB2.1@92,-10.6 C110.1@101.75,-10.6 FB3.1@103,-10.6 C107.1@112.75,-10.6 FB4.1@114,-10.6 R21.1@115.25,-10.6 116.9,-10.6 117.5,-10 v1(119.5,-10) ; v1(214.25,-10) 214.85,-10.6 C102.1@215.75,-10.6 R22.1@218.25,-10.6 C108.1@237.75,-10.6 R62.1@240.25,-10.6 242.9,-10.6 v1(243.5,-10) ; v1(338.25,-10) 338.85,-10.6 C71.1@340.75,-10.6 R70.1@343.25,-10.6 C98.1@351.75,-10.6 R79.1@354.25,-10.6 R81.1@365.25,-10.6
  Top Layer w0.762: U10.2@48.59,-38.23 U10.2@48.651,-38.291
  Mid-Layer 2 w0.508: v4(49.615,-33.168) 49.615,-46.865 54.75,-52 v2@65.541,-52 ; v2(65.5,-52) 68.744,-48.756 v1(70.705,-48.756) v1(73.242,-48.756) v1(75.765,-48.756) v1@83.246,-48.756 ; v1(83.25,-48.751) v1(88.5,-48.751) ; v1(119.5,-10) v1(214.25,-10) ; v1(243.5,-10) v1(338.25,-10)
  Bottom Layer w0.508: v4(49.615,-33.168) 49.615,-34.385 48.738,-35.262 39.512,-35.262 37.75,-33.5 37.75,-11.5 39.25,-10 v1(87.75,-10) ; v2(65.5,-52) 65.5,-57 66.25,-57.75 90.5,-57.75 93.5,-60.75 186.5,-60.75 189.417,-57.833 193.75,-57.833 ; J4.10@193.76,-59.353 193.76,-57.843 193.75,-57.833 ; J4.12@204.48,-59.353 202.96,-57.833 193.75,-57.833
  other v1: 78.25,-48.751 80.75,-48.751 86,-48.751
3.3VCC_REF: C84.2 C86.2 L6.2 U2.21 | length 6.9
  Top Layer w0.254: L6.2@102.833,-53.12 107.13,-53.12 107.795,-52.455 U2.21@109.468,-52.455
28VIN: C64.1 C65.2 C87.1 C88.2 C89.2 C100.2 C101.2 R83.1 R89.1 R90.1 R97.1 R98.1 R170.1 R171.1 R172.1 R173.1 TP3.1 TP4.1 TP5.1 TP6.1 TP7.1 TP8.1 TP15.1 TP16.1 U9.1 U14.1 U14.2 U15.1 U15.2 U18.1 U18.2 U19.1 U19.2 | length 7.3
  Top Layer w0.381: R83.1@94.45,-34.25 v1(95.5,-34.25)
  Bottom Layer w0.381: v1(95.5,-34.25) v2(95.5,-28)
  other v2: 43.723,-19.78 44.739,-19.78 169.374,-19.78 170.39,-19.78 293.326,-19.78 294.342,-19.78 418.388,-19.69 419.404,-19.69
28VOUT1: pad.@14,-4.921 pad.@72,-4.921 R89.2 R170.2 U14.8 | length 1.4
  Bottom Layer w0.381: U14.8@44.993,-12.839 v1(44.993,-11.449)
28VOUT2: pad.@139,-4.921 pad.@197,-4.813 R97.2 R172.2 U18.8 | length 1.4
  Bottom Layer w0.381: U18.8@170.644,-12.839 v1(170.644,-11.449)
28VOUT3: pad.@264,-4.813 pad.@322,-4.921 R90.2 R171.2 U15.8 | length 1.4
  Bottom Layer w0.381: U15.8@294.596,-12.839 v1(294.596,-11.449)
28VOUT4: pad.@389,-4.794 pad.@447,-4.794 R98.2 R173.2 U19.8 | length 1.4
  Bottom Layer w0.508: U19.8@419.658,-12.749 v1(419.658,-11.376)
+5V: C22.2 C23.2 C43.2 C66.2 C73.2 C77.2 C79.2 C80.2 C129.2 C182.2 C184.2 C185.2 C2001.2 C2002.1 C2003.2 C2004.2 C2005.1 C2006.1 C2007.1 C2015.2 C2016.1 C2017.2 C2018.2 C2019.1 C2020.1 C2021.1 R167.2 R2005.2 R2015.1 R2020.2 R2035.1 U10.3 U11.3 U25.2 U2001.15 U2002.8 U2003.15 U2004.8 | length 183
  Top Layer w0.254: v1@5.542,-44.925 5.542,-42.271 C2003.2@5.861,-41.953 ; C2007.1@5.861,-47.515 5.542,-47.197 v1(5.542,-44.962) C2001.2@6.33,-44.962 C2002.1@7.634,-44.962 7.926,-44.962 8.298,-44.59 U2001.15@10.19,-44.59 ; v1(15.093,-51.402) R2015.1@15.093,-50.626 ; v1@23.193,-45.021 C2015.2@23.992,-45.021 C2016.1@25.296,-45.021 25.663,-45.021 26.035,-44.65 U2003.15@27.675,-44.65 ; C2021.1@23.523,-47.575 C2018.2@23.523,-46.33 23.179,-45.987 v1(23.179,-45.035) 23.179,-42.356 C2017.2@23.523,-42.012
  Top Layer w0.5: v1(32.75,-51.5) R2035.1@32.75,-50.6
  Top Layer w0.508: U2002.8@11.922,-28.304 11.922,-27.554 11.965,-27.511 11.976,-27.511 12.915,-26.573 13.284,-26.573 13.43,-26.427 C2005.1@13.43,-26.377 13.455,-26.402 15.005,-26.402 C2006.1@15.03,-26.427 14.984,-26.473 14.984,-27.831 v4(14.938,-27.877) ; R2005.2@15.94,-34.5 v1(16.84,-34.5) ; U2004.8@29.559,-28.277 29.559,-27.537 30.796,-26.3 C2020.1@32.605,-26.3 C2020.1@32.855,-26.3 ; v4@32.63,-27.825 C2020.1@32.63,-26.325 ; v4(32.655,-27.85) 34.85,-27.85 36.1,-29.1 36.1,-34.5 ; R2020.2@33.6,-34.5 36.1,-34.5 ; C23.2@45.114,-35.262 42.262,-35.262 41.5,-34.5 37.5,-34.5 36.1,-34.5 ; R167.2@58.098,-33.905 C184.2@58.098,-35.366 60.24,-35.366 C129.2@60.427,-35.179
  Top Layer w0.635: U10.3@46.29,-38.23 46.523,-38.462 46.523,-38.773 47.767,-40.017 49.615,-40.017 51.348,-41.75 60.5,-41.75 ; C129.2@60.427,-35.241 v4(60.427,-36.826) U25.2@60.427,-38.455 60.427,-41.677 60.5,-41.75 ; C79.2@74,-39.6 64.9,-39.6 62.75,-41.75 60.5,-41.75 ; C79.2@74.025,-39.575 75.75,-39.575 77.5,-39.575 81.1,-39.575 U11.3@81.125,-39.55
  Mid-Layer 2 w0.5: v1(5.542,-44.962) 6.521,-45.94 15,-45.94 16.75,-45.94 23.179,-45.94 31.69,-45.94 32.75,-47 v1(32.75,-51.5)
  Mid-Layer 2 w0.508: 15,-45.94 15.093,-46.033 v1(15.093,-51.402) ; 16.75,-45.94 16.84,-45.85 16.84,-42.84 14.938,-40.938 14.938,-34.5 ; v1(16.84,-34.5) 14.938,-34.5 ; 23.179,-45.94 v1(23.179,-45.035) ; v4(32.655,-27.85) 32.642,-27.864 14.952,-27.864 v4(14.938,-27.877) 14.938,-34.5
  Bottom Layer w0.635: v4(60.427,-36.826) 60.427,-37.707 C182.2@60.474,-37.754
  other v2: 45.021,-36.903 46.147,-36.826
+5V_11: FB18.2 R181.2 U27.1 | length 2.6
  Top Layer w0.508: R181.2@237.287,-38.207 237.766,-38.207 v2(237.779,-38.221) 238.875,-38.221 FB18.2@238.888,-38.207
  Bottom Layer w0.508: U27.1@236.823,-38.166 236.848,-38.192 237.75,-38.192 v2(237.779,-38.221)
+5V_12: FB15.2 R85.2 U28.1 | length 2.8
  Top Layer w0.508: R85.2@237.21,-50.725 237.725,-50.725 v2(237.75,-50.75) 237.779,-50.721 239.15,-50.721 FB15.2@239.17,-50.7
  Bottom Layer w0.508: U28.1@236.954,-50.688 236.987,-50.721 237.721,-50.721 v2(237.75,-50.75)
